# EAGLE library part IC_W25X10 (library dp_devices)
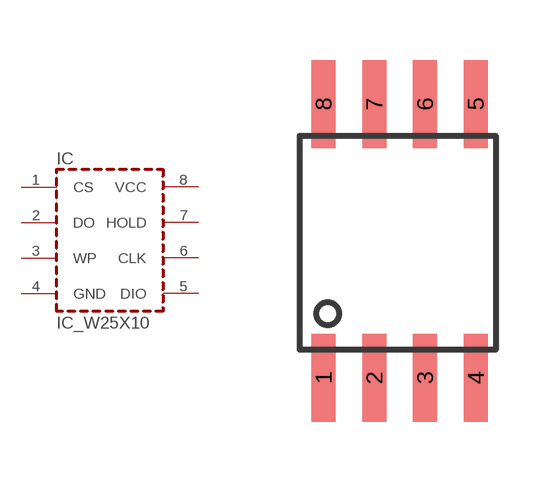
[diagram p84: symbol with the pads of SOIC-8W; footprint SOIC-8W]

Designator prefix IC

## IC_W25X10  [SOIC-8W]
1  CS
2  DO
3  WP
4  GND  pwr
5  DIO
6  CLK
7  HOLD
8  VCC  pwr

## Footprint SOIC-8W (pad centres in mm)
smd 0.6 x 2.2: 1 -1.905,-3.87; 2 -0.635,-3.87; 3 0.635,-3.87; 4 1.905,-3.87; 5 1.905,2.981; 6 0.635,2.981; 7 -0.635,2.981; 8 -1.905,2.981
